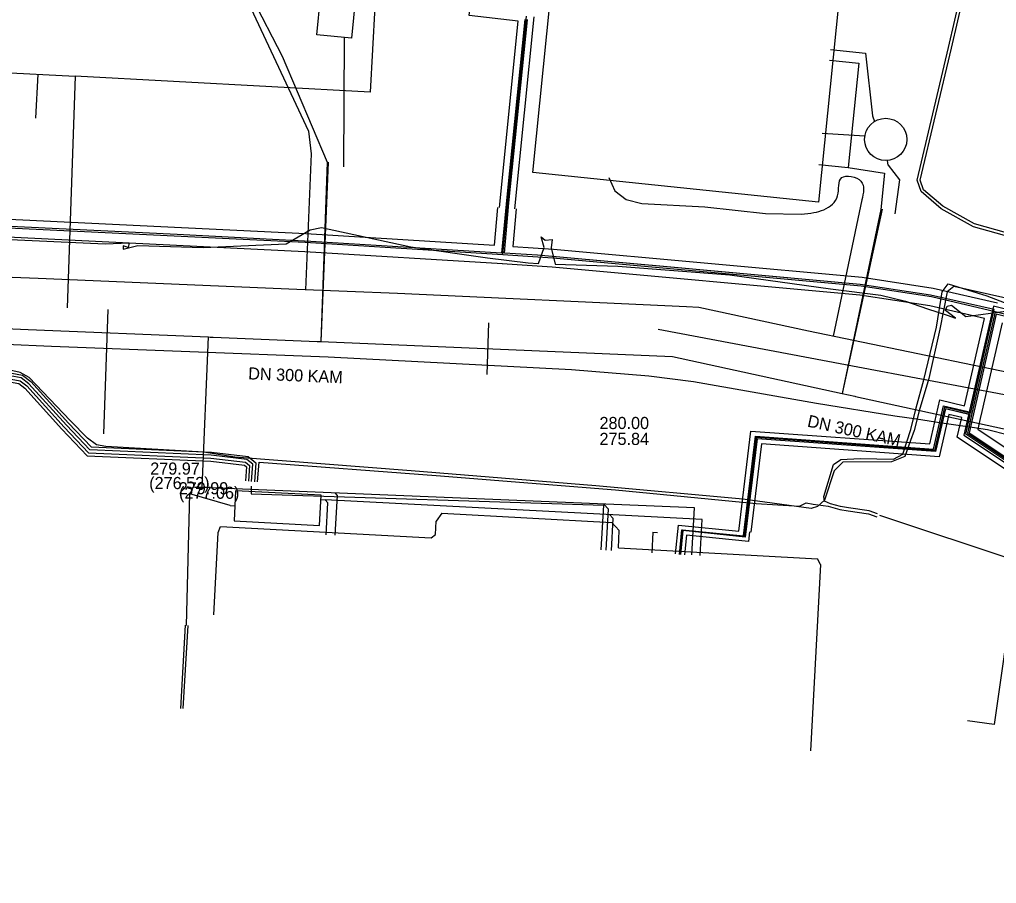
# Model space of a CAD drawing. Extents: x -598233 to -596890, y -1157848 to -1156431.
# Drawn here: x -597868 to -597803.5, y -1156848.3 to -1156791.3 of the extents above; entities that cross this region are included whole.
import ezdxf

# ---------------------------------------------------------------- set-up
doc = ezdxf.new("R2010")
doc.units = 0
for name, color, linetype in [('Vrstva 1', 7, 'Continuous'), ('Vrstva 13', 7, 'Continuous'), ('Vrstva 19', 7, 'Continuous'), ('Vrstva 25', 7, 'Continuous'), ('Vrstva 26', 7, 'Continuous'), ('Vrstva 3', 7, 'Continuous'), ('Vrstva 33', 7, 'Continuous'), ('Vrstva 34', 7, 'Continuous'), ('Vrstva 37', 7, 'Continuous'), ('Vrstva 4', 7, 'Continuous'), ('Vrstva 42', 7, 'Continuous'), ('Vrstva 44', 7, 'Continuous'), ('Vrstva 5', 7, 'Continuous'), ('Vrstva 55', 7, 'Continuous'), ('Vrstva 8', 7, 'Continuous')]:
    doc.layers.add(name, color=color, linetype=linetype)

msp = doc.modelspace()

# ---------------------------------------------------------------- linework, layer by layer
at = {"layer": 'Vrstva 1'}
for p, q in [((-597834.149, -1156801.409), (-597832.259, -1156783.024)), ((-597813.374, -1156784.653), (-597815.277, -1156803.382)), ((-597844.57, -1156790.48), (-597844.87, -1156796.11)), ((-597846.6, -1156792.493), (-597846.65, -1156801.05)), ((-597894.63, -1156793.51), (-597864.35, -1156795.06)), ((-597814.478, -1156793.299), (-597812.161, -1156793.534)), ((-597812.161, -1156793.534), (-597811.72, -1156797.67)), ((-597866.96, -1156797.84), (-597866.811, -1156794.934)), ((-597864.35, -1156795.06), (-597864.897, -1156810.353)), ((-597844.87, -1156796.11), (-597864.35, -1156795.06)), ((-597811.72, -1156797.67), (-597811.583, -1156798.059)), ((-597815.04, -1156798.831), (-597812.207, -1156798.989)), ((-597810.68, -1156800.94), (-597810.709, -1156800.621)), ((-597810.68, -1156800.94), (-597809.93, -1156801.9)), ((-597815.277, -1156803.382), (-597834.149, -1156801.409)), ((-597809.93, -1156801.9), (-597810.24, -1156804.14)), ((-597857.01, -1156831.31), (-597856.78, -1156822.63)), ((-597854.134, -1156823.402), (-597856.78, -1156822.63)), ((-597848.126, -1156822.999), (-597847.855, -1156823.014)), ((-597847.855, -1156823.014), (-597847.671, -1156823.219)), ((-597822.96, -1156824.31), (-597847.855, -1156823.014)), ((-597854.134, -1156823.402), (-597853.816, -1156823.419)), ((-597847.785, -1156825.331), (-597847.671, -1156823.219)), ((-597840.565, -1156825.301), (-597840.517, -1156824.425)), ((-597840.156, -1156823.911), (-597840.517, -1156824.425)), ((-597840.156, -1156823.911), (-597828.925, -1156824.521)), ((-597829.072, -1156823.992), (-597828.836, -1156824.255)), ((-597828.951, -1156826.37), (-597828.836, -1156824.255)), ((-597823.084, -1156826.694), (-597822.96, -1156824.31)), ((-597854.91, -1156825.17), (-597854.762, -1156824.773)), ((-597854.762, -1156824.773), (-597840.85, -1156825.54)), ((-597828.427, -1156825.047), (-597828.925, -1156824.521)), ((-597828.49, -1156826.19), (-597828.427, -1156825.047)), ((-597855.2, -1156830.62), (-597854.91, -1156825.17)), ((-597840.85, -1156825.54), (-597840.565, -1156825.301)), ((-597828.49, -1156826.19), (-597815.345, -1156826.915)), ((-597815.14, -1156827.3), (-597815.345, -1156826.915)), ((-597815.14, -1156827.3), (-597815.81, -1156839.58)), ((-597802.422, -1156829.054), (-597803.68, -1156837.86)), ((-597803.68, -1156837.86), (-597805.43, -1156837.61))]:
    msp.add_line(p, q, dxfattribs=at)
for points in [[(-597862.47, -1156818.67), (-597862.176, -1156810.451)], [(-597837.16, -1156814.76), (-597837.038, -1156811.35)], [(-597825.87, -1156811.75), (-597795.28, -1156817.53)]]:
    msp.add_lwpolyline(points, dxfattribs=at)
at = {"layer": 'Vrstva 13'}
for p, q in [((-597848.77, -1156800.18), (-597849.148, -1156809.154)), ((-597812.42, -1156803.23), (-597814.307, -1156812.221))]:
    msp.add_line(p, q, dxfattribs=at)
msp.add_lwpolyline([(-597795.967, -1156816.025), (-597812.956, -1156812.495), (-597815.93, -1156811.88), (-597823.17, -1156810.33), (-597823.982, -1156810.292), (-597843.08, -1156809.41), (-597849.715, -1156809.134), (-597866.8, -1156808.41), (-597873.134, -1156808.177), (-597894.82, -1156807.38), (-597910.254, -1156804.837)], dxfattribs=at)
at = {"layer": 'Vrstva 19'}
msp.add_lwpolyline([(-597801.34, -1156819.11), (-597804.12, -1156818.41), (-597805.138, -1156818.257), (-597807.137, -1156817.956), (-597808.811, -1156817.705), (-597810.24, -1156817.49), (-597815.41, -1156816.67), (-597823.52, -1156815.24), (-597826.48, -1156814.85), (-597831.59, -1156814.44), (-597847.65, -1156813.6), (-597865.92, -1156812.91), (-597868.94, -1156812.78), (-597886.35, -1156812.11), (-597899.95, -1156811.51), (-597902.9, -1156811.28), (-597907.18, -1156810.68), (-597910.13, -1156810.14), (-597910.52, -1156810.07), (-597913.04, -1156809.59), (-597914.47, -1156809.33), (-597914.91, -1156809.25)], dxfattribs=at)
at = {"layer": 'Vrstva 25'}
for p, q in [((-597835.844, -1156803.771), (-597834.561, -1156791.097)), ((-597836.113, -1156806.847), (-597835.844, -1156803.771)), ((-597803.601, -1156810.605), (-597805.147, -1156817.335))]:
    msp.add_line(p, q, dxfattribs=at)
for points in [[(-597778.89, -1156783.904), (-597786.068, -1156790.954), (-597790.337, -1156796.407), (-597793.062, -1156801.571), (-597797.61, -1156812.112), (-597803.601, -1156810.605)], [(-597836.113, -1156806.847), (-597849.17, -1156806.043), (-597869.696, -1156805.05), (-597883.904, -1156804.353), (-597887.574, -1156828.509)], [(-597803.601, -1156810.605), (-597807.821, -1156809.632), (-597812.464, -1156808.921), (-597832.821, -1156807.069), (-597836.113, -1156806.847)], [(-597805.147, -1156817.335), (-597806.959, -1156816.91), (-597807.613, -1156819.761), (-597819.388, -1156818.907), (-597820.133, -1156825.111)], [(-597805.147, -1156817.335), (-597805.438, -1156818.627), (-597787.655, -1156830.499)], [(-597820.133, -1156825.111), (-597820.167, -1156825.437), (-597824.26, -1156825.02), (-597824.423, -1156826.62)]]:
    msp.add_lwpolyline(points, dxfattribs=at)
at = {"layer": 'Vrstva 26'}
for p, q in [((-597836.342, -1156803.721), (-597835.098, -1156791.437)), ((-597834.064, -1156791.147), (-597835.347, -1156803.821)), ((-597836.66, -1156806.213), (-597836.442, -1156803.719)), ((-597835.247, -1156803.823), (-597835.462, -1156806.29)), ((-597805.641, -1156816.808), (-597804.32, -1156811.055)), ((-597803.153, -1156811.337), (-597804.562, -1156817.469))]:
    msp.add_line(p, q, dxfattribs=at)
for points in [[(-597835.098, -1156791.437), (-597838.335, -1156791.058), (-597837.542, -1156783.995), (-597832.223, -1156784.525)], [(-597888.167, -1156828.419), (-597884.416, -1156803.727), (-597869.666, -1156804.45), (-597849.137, -1156805.444), (-597836.66, -1156806.213)], [(-597836.15, -1156807.446), (-597849.203, -1156806.642), (-597869.725, -1156805.649), (-597883.393, -1156804.978), (-597886.98, -1156828.599)], [(-597835.462, -1156806.29), (-597832.773, -1156806.47), (-597812.391, -1156808.325), (-597807.708, -1156809.043), (-597803.466, -1156810.021)], [(-597804.32, -1156811.055), (-597807.934, -1156810.222), (-597812.536, -1156809.517), (-597832.868, -1156807.667), (-597836.154, -1156807.446)], [(-597820.534, -1156825.098), (-597819.74, -1156818.48), (-597807.926, -1156819.337), (-597807.259, -1156816.429), (-597805.641, -1156816.808)], [(-597805.819, -1156817.588), (-597806.659, -1156817.391), (-597807.3, -1156820.184), (-597819.036, -1156819.334), (-597819.736, -1156825.159)], [(-597788.258, -1156830.818), (-597806.114, -1156818.897), (-597805.819, -1156817.588)], [(-597804.561, -1156817.467), (-597804.762, -1156818.357), (-597787.322, -1156830)], [(-597824.722, -1156826.59), (-597824.528, -1156824.691), (-597820.534, -1156825.098)], [(-597819.835, -1156825.142), (-597819.899, -1156825.766), (-597823.992, -1156825.349), (-597824.125, -1156826.651)]]:
    msp.add_lwpolyline(points, dxfattribs=at)
at = {"layer": 'Vrstva 3'}
for p, q in [((-597848.4, -1156792.32), (-597847.94, -1156787.57)), ((-597845.65, -1156787.78), (-597846.11, -1156792.54)), ((-597846.11, -1156792.54), (-597848.4, -1156792.32)), ((-597853.763, -1156822.42), (-597853.87, -1156824.418)), ((-597848.111, -1156822.725), (-597853.763, -1156822.42)), ((-597848.219, -1156824.722), (-597848.111, -1156822.725)), ((-597853.87, -1156824.418), (-597848.219, -1156824.722)), ((-597857.09, -1156831.304), (-597857.41, -1156836.795)), ((-597856.93, -1156831.313), (-597857.25, -1156836.802))]:
    msp.add_line(p, q, dxfattribs=at)
msp.add_circle((-597810.836, -1156799.234), 1.393, dxfattribs=at)
at = {"layer": 'Vrstva 33'}
for p, q in [((-597853.46, -1156789.08), (-597848.955, -1156798.699)), ((-597848.955, -1156798.699), (-597848.77, -1156800.18)), ((-597829.11, -1156801.75), (-597828.72, -1156802.62)), ((-597828.72, -1156802.62), (-597827.98, -1156803.2)), ((-597827.98, -1156803.2), (-597826.95, -1156803.47)), ((-597826.95, -1156803.47), (-597822.78, -1156803.69)), ((-597822.78, -1156803.69), (-597818.78, -1156804.13)), ((-597818.78, -1156804.13), (-597816.42, -1156804.17)), ((-597826.205, -1156825.164), (-597826.279, -1156826.518)), ((-597826.205, -1156825.164), (-597825.91, -1156825.18))]:
    msp.add_line(p, q, dxfattribs=at)
msp.add_open_spline([(-597816.42, -1156804.17), (-597815.785, -1156804.099), (-597814.888, -1156803.998), (-597813.762, -1156803.084), (-597814.157, -1156801.406), (-597812.064, -1156801.827), (-597812.302, -1156802.765), (-597812.42, -1156803.23)], degree=3, dxfattribs=at)
at = {"layer": 'Vrstva 34'}
for p, q in [((-597852.728, -1156822.114), (-597852.728, -1156822.631)), ((-597852.728, -1156822.631), (-597829.473, -1156823.371)), ((-597829.473, -1156823.371), (-597829.646, -1156826.332))]:
    msp.add_line(p, q, dxfattribs=at)
at = {"layer": 'Vrstva 37'}
for points in [[(-597767.025, -1156795.926), (-597772.674, -1156790.284), (-597778.916, -1156784.069), (-597785.893, -1156790.945), (-597790.102, -1156796.296), (-597792.987, -1156801.653), (-597797.51, -1156812.135), (-597797.755, -1156812.235), (-597803.539, -1156810.773), (-597805.328, -1156818.594), (-597787.882, -1156830.226), (-597763.487, -1156846.481), (-597751.538, -1156854.437), (-597746.376, -1156846.168), (-597743.134, -1156839.665), (-597741.9, -1156825.689), (-597738.583, -1156825.835), (-597737.777, -1156819.205), (-597719.217, -1156820.861), (-597716.427, -1156797.002), (-597711.316, -1156797.169)], [(-597834.656, -1156791.321), (-597835.862, -1156803.035), (-597836.208, -1156806.736), (-597848.804, -1156805.961), (-597857.619, -1156805.511), (-597872.759, -1156804.783), (-597883.997, -1156804.232), (-597886.045, -1156817.593), (-597887.688, -1156828.492)], [(-597824.462, -1156826.617), (-597824.287, -1156825.003), (-597820.221, -1156825.406), (-597819.437, -1156818.81), (-597807.675, -1156819.672), (-597807.029, -1156816.811), (-597805.219, -1156817.245), (-597803.671, -1156810.459), (-597807.885, -1156809.507), (-597812.518, -1156808.807), (-597825.275, -1156807.651), (-597833.831, -1156806.866), (-597836.016, -1156806.743), (-597835.726, -1156803.415), (-597834.492, -1156791.327)], [(-597711.312, -1156797.334), (-597716.315, -1156797.171), (-597719.07, -1156821.031), (-597737.648, -1156819.366), (-597738.454, -1156825.979), (-597741.773, -1156825.84), (-597742.996, -1156839.688), (-597746.272, -1156846.295), (-597751.525, -1156854.716), (-597768.595, -1156843.317), (-597790.23, -1156828.893), (-597805.551, -1156818.679), (-597805.256, -1156817.404), (-597806.893, -1156817.007), (-597807.544, -1156819.843), (-597819.331, -1156818.991), (-597820.118, -1156825.479), (-597824.24, -1156825.054), (-597824.389, -1156826.623)]]:
    msp.add_lwpolyline(points, dxfattribs=at)
at = {"layer": 'Vrstva 42'}
msp.add_line((-597811.238, -1156824.034), (-597793.526, -1156829.925), dxfattribs=at)
for points in [[(-597801.495, -1156805.987), (-597805.048, -1156804.993), (-597807.177, -1156803.813), (-597808.506, -1156802.678), (-597808.764, -1156801.925), (-597806.687, -1156793.167), (-597805.018, -1156785.931), (-597804.279, -1156780.995), (-597804.164, -1156780.871), (-597803.623, -1156780.283), (-597803.415, -1156780.219)], [(-597767.03, -1156795.93), (-597772.67, -1156790.28), (-597778.92, -1156784.07), (-597785.89, -1156790.94), (-597790.1, -1156796.3), (-597792.99, -1156801.65), (-597797.51, -1156812.13), (-597797.75, -1156812.23), (-597803.54, -1156810.77), (-597805.33, -1156818.59), (-597787.88, -1156830.23), (-597763.49, -1156846.48), (-597751.54, -1156854.44), (-597746.38, -1156846.17), (-597743.13, -1156839.66), (-597741.9, -1156825.69), (-597738.58, -1156825.83), (-597737.78, -1156819.2), (-597719.22, -1156820.86), (-597716.43, -1156797), (-597711.32, -1156797.17)], [(-597801.445, -1156805.793), (-597804.972, -1156804.807), (-597807.063, -1156803.647), (-597808.334, -1156802.562), (-597808.556, -1156801.915), (-597806.493, -1156793.213), (-597804.822, -1156785.969)], [(-597834.66, -1156791.32), (-597835.86, -1156803.04), (-597836.21, -1156806.74), (-597848.8, -1156805.96), (-597857.62, -1156805.51), (-597872.76, -1156804.78), (-597884, -1156804.23), (-597886.05, -1156817.59), (-597887.69, -1156828.49)], [(-597824.46, -1156826.62), (-597824.29, -1156825), (-597820.22, -1156825.41), (-597819.44, -1156818.81), (-597807.68, -1156819.67), (-597807.03, -1156816.81), (-597805.22, -1156817.25), (-597803.67, -1156810.46), (-597807.89, -1156809.51), (-597812.52, -1156808.81), (-597825.28, -1156807.65), (-597833.83, -1156806.87), (-597836.02, -1156806.74), (-597835.73, -1156803.42), (-597834.49, -1156791.33)], [(-597711.31, -1156797.33), (-597716.31, -1156797.17), (-597719.07, -1156821.03), (-597737.65, -1156819.37), (-597738.45, -1156825.98), (-597741.77, -1156825.84), (-597743, -1156839.69), (-597746.27, -1156846.3), (-597751.53, -1156854.72), (-597768.59, -1156843.32), (-597790.23, -1156828.89), (-597805.55, -1156818.68), (-597805.26, -1156817.4), (-597806.89, -1156817.01), (-597807.54, -1156819.84), (-597819.33, -1156818.99), (-597820.12, -1156825.48), (-597824.24, -1156825.05), (-597824.39, -1156826.62)], [(-597904.27, -1156800.31), (-597903.259, -1156801.97), (-597903.1, -1156802.23), (-597902.173, -1156802.884), (-597901.164, -1156803.596), (-597901.462, -1156804.692), (-597901.941, -1156807.307), (-597902.471, -1156810.572), (-597902.597, -1156812.034), (-597902.174, -1156812.665), (-597897.283, -1156812.92), (-597887.774, -1156813.5), (-597878.107, -1156813.96), (-597872.953, -1156814.16), (-597870.102, -1156814.382), (-597867.837, -1156814.787), (-597867.277, -1156815.207), (-597864.79, -1156817.956), (-597863.296, -1156819.535), (-597855.354, -1156819.871), (-597852.938, -1156820.162), (-597852.423, -1156820.58), (-597852.521, -1156821.826)], [(-597852.72, -1156821.81), (-597852.63, -1156820.669), (-597853.019, -1156820.354), (-597855.386, -1156820.07), (-597863.385, -1156819.732), (-597864.937, -1156818.092), (-597867.412, -1156815.356), (-597867.919, -1156814.976), (-597870.127, -1156814.581), (-597872.964, -1156814.36), (-597878.116, -1156814.16), (-597887.785, -1156813.7), (-597897.294, -1156813.12), (-597902.284, -1156812.86), (-597902.803, -1156812.086), (-597902.669, -1156810.548), (-597902.139, -1156807.273), (-597901.658, -1156804.648), (-597901.37, -1156803.592), (-597902.173, -1156802.884), (-597902.45, -1156802.64)], [(-597814.48, -1156823.29), (-597814.87, -1156823.1), (-597814.93, -1156822.81), (-597814.28, -1156820.68), (-597813.81, -1156820.35), (-597812.53, -1156820.3), (-597810.33, -1156820.34), (-597809.71, -1156820.01), (-597809.17, -1156818.39), (-597808.83, -1156816.95), (-597808.32, -1156815.11), (-597807.48, -1156811.62), (-597807.12, -1156809.3), (-597806.72, -1156808.76), (-597804.17, -1156809.56), (-597802.05, -1156810.38)], [(-597797.75, -1156811.71), (-597803.73, -1156810.24), (-597805.67, -1156818.76), (-597787.78, -1156830.66)], [(-597903.291, -1156817.318), (-597903.16, -1156816.109), (-597902.991, -1156813.905), (-597902.859, -1156813.347), (-597902.633, -1156813.215), (-597902.394, -1156813.054), (-597897.306, -1156813.32), (-597887.795, -1156813.9), (-597878.124, -1156814.36), (-597872.976, -1156814.56), (-597870.153, -1156814.779), (-597868.001, -1156815.164), (-597867.548, -1156815.504), (-597865.083, -1156818.228), (-597863.475, -1156819.928), (-597855.402, -1156820.27), (-597853.101, -1156820.546), (-597852.838, -1156820.758), (-597852.919, -1156821.794)], [(-597903.094, -1156817.355), (-597902.961, -1156816.128), (-597902.793, -1156813.936), (-597902.685, -1156813.476), (-597902.527, -1156813.385), (-597902.338, -1156813.258), (-597897.317, -1156813.52), (-597887.806, -1156814.1), (-597878.133, -1156814.56), (-597872.987, -1156814.76), (-597870.178, -1156814.978), (-597868.083, -1156815.353), (-597867.683, -1156815.653), (-597865.23, -1156818.364), (-597863.564, -1156820.125), (-597855.403, -1156820.47), (-597853.182, -1156820.738), (-597853.046, -1156820.848), (-597853.119, -1156821.779)], [(-597852.321, -1156821.841), (-597852.219, -1156820.538), (-597840.53, -1156821.41), (-597828.67, -1156822.37), (-597819.4, -1156823.26), (-597816.527, -1156823.436), (-597816.09, -1156823.21), (-597815.62, -1156823.3)], [(-597815.62, -1156823.3), (-597814.644, -1156823.443), (-597813.868, -1156823.658), (-597813.326, -1156823.759), (-597811.984, -1156823.938), (-597811.413, -1156824.142)], [(-597811.387, -1156823.938), (-597811.936, -1156823.742), (-597813.294, -1156823.561), (-597813.832, -1156823.462), (-597814.48, -1156823.29)]]:
    msp.add_lwpolyline(points, dxfattribs=at)
at = {"layer": 'Vrstva 44'}
msp.add_lwpolyline([(-597801.62, -1156810), (-597806.33, -1156808.95), (-597806.78, -1156809.29), (-597807.26, -1156811.75), (-597808, -1156815.01), (-597808.62, -1156817.14), (-597808.96, -1156818.44), (-597809.2, -1156819.1), (-597809.57, -1156820.16), (-597810.45, -1156820.51), (-597813.66, -1156820.54), (-597814.23, -1156821.1), (-597814.87, -1156823.04), (-597815.34, -1156823.47), (-597815.77, -1156823.6), (-597820.27, -1156822.98), (-597829.98, -1156822.1), (-597842.17, -1156821.11), (-597853.82, -1156820.2), (-597855.87, -1156819.87), (-597862.33, -1156819.51), (-597862.95, -1156819.39), (-597863.54, -1156818.96), (-597864.68, -1156817.78), (-597867.4, -1156814.94), (-597867.99, -1156814.61), (-597868.67, -1156814.46)], dxfattribs=at)
at = {"layer": 'Vrstva 5'}
for p, q in [((-597853.25, -1156788.77), (-597850.68, -1156793.73)), ((-597850.68, -1156793.73), (-597847.71, -1156800.74)), ((-597814.549, -1156794.002), (-597812.621, -1156794.198)), ((-597812.621, -1156794.198), (-597813.32, -1156801.08)), ((-597847.71, -1156800.74), (-597848.148, -1156812.582)), ((-597847.65, -1156800.74), (-597848.148, -1156812.582)), ((-597815.249, -1156800.884), (-597813.32, -1156801.08)), ((-597813.32, -1156801.08), (-597810.91, -1156801.46)), ((-597810.91, -1156801.46), (-597811.16, -1156803.86)), ((-597811.07, -1156803.84), (-597813.719, -1156815.998)), ((-597811.16, -1156803.86), (-597813.719, -1156815.998)), ((-597901.13, -1156810.41), (-597867.46, -1156811.77)), ((-597855.97, -1156822.2), (-597855.552, -1156812.271)), ((-597855.97, -1156822.2), (-597855.552, -1156812.271)), ((-597823.47, -1156823.55), (-597855.97, -1156822.2)), ((-597847.044, -1156822.727), (-597847.187, -1156822.565)), ((-597847.186, -1156825.364), (-597847.044, -1156822.727)), ((-597829.451, -1156823.302), (-597829.151, -1156823.635)), ((-597829.298, -1156826.351), (-597829.151, -1156823.635)), ((-597823.642, -1156826.663), (-597823.47, -1156823.55))]:
    msp.add_line(p, q, dxfattribs=at)
for points in [[(-597867.46, -1156811.77), (-597855.552, -1156812.271), (-597855.439, -1156812.276), (-597855.242, -1156812.284), (-597848.386, -1156812.572), (-597848.258, -1156812.578), (-597848.148, -1156812.582), (-597824.91, -1156813.56)], [(-597824.91, -1156813.56), (-597813.719, -1156815.998), (-597812.877, -1156816.181), (-597812.827, -1156816.192), (-597794.43, -1156820.2)]]:
    msp.add_lwpolyline(points, dxfattribs=at)
at = {"layer": 'Vrstva 55'}
for points in [[(-597869.65, -1156805.8), (-597862.37, -1156806.13), (-597860.8, -1156806.06), (-597860.85, -1156806.36), (-597861.18, -1156806.25), (-597861.18, -1156806.48), (-597860.22, -1156806.24), (-597855.9, -1156806.36), (-597850.43, -1156806.13), (-597848.85, -1156805.2), (-597848.1, -1156805.05), (-597842.19, -1156806.33), (-597837.13, -1156807.05), (-597834.44, -1156807.39), (-597833.77, -1156807.43), (-597833.38, -1156806.36), (-597833.59, -1156805.66), (-597833.32, -1156805.89), (-597832.87, -1156805.83), (-597832.92, -1156806.38), (-597832.67, -1156807.47), (-597828.53, -1156807.59), (-597821.14, -1156808.17), (-597814.48, -1156809.09), (-597811.15, -1156809.52), (-597809.52, -1156809.92), (-597808.07, -1156810.41), (-597806.77, -1156810.84), (-597806.23, -1156811.04)], [(-597869.65, -1156805.8), (-597862.37, -1156806.13), (-597860.8, -1156806.06), (-597860.85, -1156806.36), (-597861.18, -1156806.25), (-597861.18, -1156806.48), (-597860.22, -1156806.24), (-597855.9, -1156806.36), (-597850.43, -1156806.13), (-597848.85, -1156805.2), (-597848.1, -1156805.05), (-597842.19, -1156806.33), (-597837.13, -1156807.05), (-597834.44, -1156807.39), (-597833.77, -1156807.43), (-597833.38, -1156806.36), (-597833.59, -1156805.66), (-597833.32, -1156805.89), (-597832.87, -1156805.83), (-597832.92, -1156806.38), (-597832.67, -1156807.47), (-597828.53, -1156807.59), (-597821.14, -1156808.17), (-597814.48, -1156809.09), (-597811.15, -1156809.52), (-597809.52, -1156809.92), (-597808.07, -1156810.41), (-597806.77, -1156810.84), (-597806.23, -1156811.04), (-597806.9, -1156810.52), (-597806.79, -1156810.25), (-597806.5, -1156810.18), (-597805.54, -1156810.93), (-597802.93, -1156810.57)], [(-597869.65, -1156805.8), (-597862.37, -1156806.13), (-597860.8, -1156806.06), (-597860.85, -1156806.36), (-597861.18, -1156806.25), (-597861.18, -1156806.48), (-597860.22, -1156806.24), (-597855.9, -1156806.36), (-597850.43, -1156806.13), (-597848.85, -1156805.2), (-597848.1, -1156805.05), (-597842.19, -1156806.33), (-597837.13, -1156807.05), (-597834.44, -1156807.39), (-597833.77, -1156807.43), (-597833.38, -1156806.36), (-597833.59, -1156805.66), (-597833.32, -1156805.89), (-597832.87, -1156805.83), (-597832.92, -1156806.38), (-597832.67, -1156807.47), (-597828.53, -1156807.59), (-597821.14, -1156808.17), (-597814.48, -1156809.09), (-597811.15, -1156809.52), (-597809.52, -1156809.92), (-597808.07, -1156810.41), (-597806.77, -1156810.84), (-597806.23, -1156811.04), (-597806.9, -1156810.52), (-597806.79, -1156810.25), (-597806.5, -1156810.18), (-597805.54, -1156810.93), (-597802.93, -1156810.57)], [(-597806.23, -1156811.04), (-597806.9, -1156810.52), (-597806.79, -1156810.25), (-597806.5, -1156810.18), (-597805.54, -1156810.93), (-597802.93, -1156810.57), (-597799.58, -1156809.57), (-597797.36, -1156807.79), (-597796.9, -1156806.55), (-597787.26, -1156810.07), (-597786.26, -1156810.3)]]:
    msp.add_lwpolyline(points, dxfattribs=at)

# ---------------------------------------------------------------- texts
at = {"layer": 'Vrstva 4'}
for s, p in [('279.99', (-597857.522, -1156822.657)), ('(277.06)', (-597857.501, -1156822.953))]:
    msp.add_text(s, height=0.8, dxfattribs=at).set_placement(p)
at = {"layer": 'Vrstva 8'}
for rotation, p in [(357.59109, (-597852.945, -1156815.069)), (347.71026, (-597816.058, -1156818.181))]:
    msp.add_text('DN 300 KAM', height=0.8, rotation=rotation, dxfattribs=at).set_placement(p)
for s, p in [('280.00', (-597829.736, -1156818.35)), ('275.84', (-597829.736, -1156819.4)), ('279.97', (-597859.401, -1156821.36)), ('(276.52)', (-597859.468, -1156822.313))]:
    msp.add_text(s, height=0.8, dxfattribs=at).set_placement(p)

doc.saveas('drawing.dxf')
